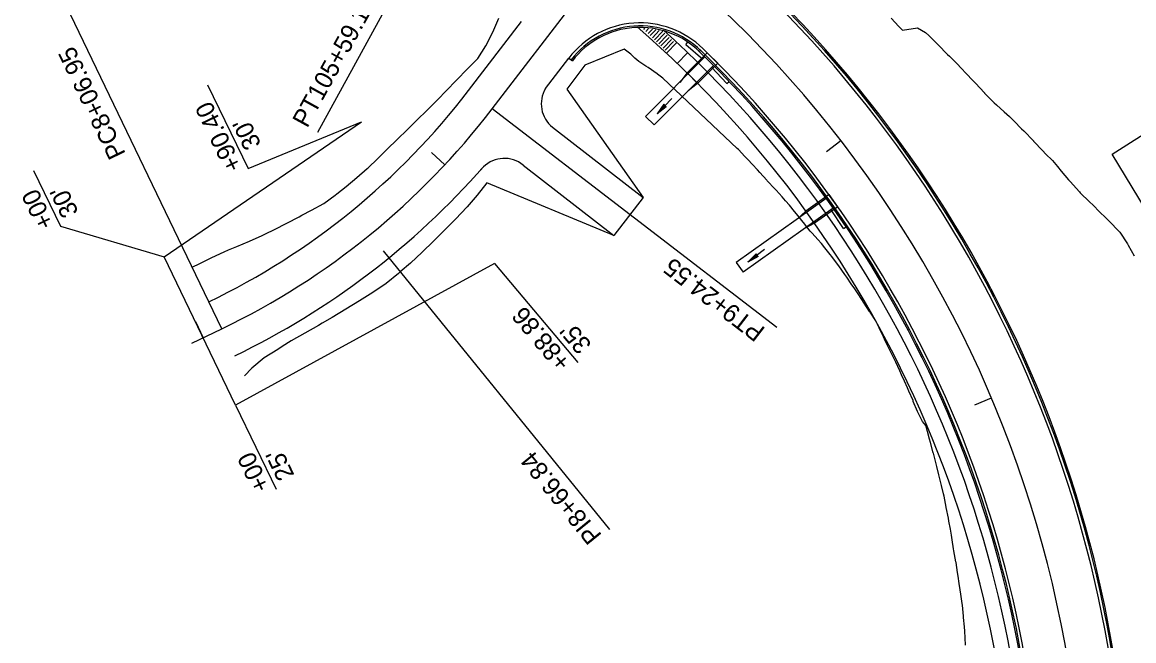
# Model space of a CAD drawing. Extents: x 1098669 to 1198896, y 698679 to 704410.
# Drawn here: x 1108421.2 to 1108793, y 699589.1 to 699795.9 of the extents above; entities that cross this region are included whole.
import ezdxf

# ---------------------------------------------------------------- set-up
doc = ezdxf.new("R2010")
doc.units = 0
for name, color, linetype in [('R_50 Horz Alg PC PI PT', 7, 'Continuous'), ('R_50 Horz Alg Ticks', 7, 'Continuous'), ('R_Horz Alg', 7, 'Continuous'), ('R_No Plot', 7, 'Continuous'), ('R_Proposed Const Limits', 7, 'Continuous'), ('R_Proposed Curb', 7, 'Continuous'), ('R_Proposed Road', 7, 'Continuous'), ('R_Proposed Sidewalk', 7, 'Continuous'), ('R_ROW', 7, 'Continuous'), ('R_ROW Annot', 7, 'Continuous'), ('R_Water', 7, 'Continuous')]:
    doc.layers.add(name, color=color, linetype=linetype)

msp = doc.modelspace()

# ---------------------------------------------------------------- linework, layer by layer
at = {"layer": 'R_50 Horz Alg PC PI PT'}
msp.add_line((1108574.89, 699859.09), (1108519.93, 699759.09), dxfattribs=at)
for points in [[(1108487.97, 699693.42), (1108435.87, 699801.52)], [(1108673.58, 699693.87), (1108578.4, 699766.94)], [(1108541.92, 699719.43), (1108617.62, 699626.32)], [(1108541.92, 699719.43), (1108617.62, 699626.32)]]:
    msp.add_lwpolyline(points, dxfattribs=at)
at = {"layer": 'R_50 Horz Alg Ticks'}
for points in [[(1108558.14, 699752.32), (1108562.52, 699748.22)], [(1108479.11, 699695.81), (1108481.71, 699690.41)]]:
    msp.add_lwpolyline(points, dxfattribs=at)
at = {"layer": 'R_Horz Alg'}
for p, q in [((1108578.4, 699766.94), (1108678.27, 699897.05)), ((1108690.25, 699752.74), (1108694.99, 699756.41)), ((1108477.94, 699688.59), (1108487.97, 699693.42)), ((1108739.88, 699668.02), (1108745.4, 699670.36))]:
    msp.add_line(p, q, dxfattribs=at)
for centre, radius, start, end in [((1108387.8, 699518.66), 388.45, 355.801, 61.2087), ((1108378.62, 699920.3), 251.85, 295.7332, 322.4881)]:
    msp.add_arc(centre, radius, start, end, dxfattribs=at)
at = {"layer": 'R_Proposed Const Limits'}
for points in [[(1108478.03, 699714.05), (1108480.54, 699715.23), (1108484.63, 699717.22), (1108488.74, 699719.19), (1108490.13, 699719.77), (1108492.98, 699720.95), (1108497.22, 699722.74), (1108501.43, 699724.64), (1108502.55, 699725.18), (1108505.59, 699726.66), (1108509.73, 699728.75), (1108513.86, 699730.89), (1108514.73, 699731.35), (1108517.98, 699733.09), (1108522.1, 699735.34), (1108525.85, 699738.1), (1108526.4, 699738.53), (1108529.49, 699741), (1108533.06, 699743.97), (1108536.62, 699746.98), (1108536.93, 699747.26), (1108539.99, 699750.19), (1108543.27, 699753.49), (1108546.65, 699756.7), (1108546.75, 699756.79), (1108550, 699759.94), (1108553.27, 699763.27), (1108556.52, 699766.44), (1108556.61, 699766.54), (1108559.94, 699769.85), (1108563.24, 699773.19), (1108566.23, 699776.28), (1108566.54, 699776.61), (1108570.04, 699780.22), (1108573.59, 699783.8), (1108576.29, 699788.03), (1108578.57, 699792.58), (1108580.65, 699797.29)], [(1108711.82, 699797.24), (1108714.39, 699794.49), (1108715.64, 699793.26), (1108720.62, 699793.99), (1108723.35, 699792.46), (1108724.43, 699791.42), (1108727.37, 699788.53), (1108727.6, 699788.3), (1108730.75, 699785.15), (1108731.35, 699784.55), (1108733.89, 699781.97), (1108735.3, 699780.52), (1108737.01, 699778.77), (1108739.22, 699776.45), (1108740.09, 699775.52), (1108743.05, 699772.3), (1108743.12, 699772.22), (1108746.27, 699769), (1108747.1, 699768.27), (1108749.69, 699765.94), (1108751.4, 699764.38), (1108753.04, 699762.8), (1108755.5, 699760.31), (1108756.25, 699759.55), (1108759.43, 699756.26), (1108759.52, 699756.16), (1108762.58, 699752.92), (1108763.49, 699751.94), (1108765.82, 699749.63), (1108767.47, 699747.7), (1108768.78, 699746.14), (1108771.17, 699743.25), (1108771.7, 699742.61), (1108774.85, 699739.18), (1108775.12, 699738.92), (1108778.23, 699735.87), (1108779.39, 699734.72), (1108781.61, 699732.52), (1108783.65, 699730.47), (1108784.98, 699729.14), (1108787.88, 699726.16), (1108788.32, 699725.71), (1108790.88, 699721.85), (1108791.18, 699721.32), (1108793.16, 699717.85)], [(1108622.58, 699786.85), (1108609.38, 699781.54), (1108606.34, 699777.57), (1108603.39, 699773.53), (1108628.92, 699737.28)], [(1108635.45, 699777.18), (1108633.67, 699778.55), (1108633.56, 699778.62), (1108630.53, 699780.72), (1108629.84, 699781.19), (1108627.47, 699782.76), (1108626.12, 699783.93), (1108624.77, 699785.2), (1108622.58, 699786.85)], [(1108736.78, 699587.68), (1108736.62, 699590.06), (1108736.46, 699592.3), (1108736.35, 699593.72), (1108736.11, 699596.92), (1108736.06, 699597.38), (1108735.7, 699601.03), (1108735.63, 699601.53), (1108735.19, 699604.66), (1108734.98, 699606.11), (1108734.66, 699608.29), (1108734.3, 699610.7), (1108734.11, 699611.93), (1108733.56, 699615.28), (1108733.51, 699615.55), (1108732.88, 699619.18), (1108732.77, 699619.87), (1108732.28, 699622.83), (1108732.01, 699624.47), (1108731.66, 699626.48), (1108731.21, 699629.09), (1108731.01, 699630.13), (1108730.32, 699633.68), (1108730.3, 699633.77), (1108729.58, 699637.42), (1108729.4, 699638.29), (1108728.74, 699641.03), (1108728.29, 699642.84), (1108727.84, 699644.64), (1108727.14, 699647.4), (1108726.92, 699648.24), (1108725.98, 699651.85), (1108725.95, 699651.95), (1108725.01, 699655.45), (1108724.73, 699656.5), (1108724.03, 699659.06), (1108723.48, 699661.07), (1108722.37, 699662.39), (1108720.98, 699665.09), (1108720.72, 699665.72), (1108719.28, 699669.14), (1108719.17, 699669.41), (1108717.82, 699672.55), (1108717.3, 699673.72), (1108716.3, 699675.94), (1108715.37, 699677.99), (1108714.75, 699679.32), (1108713.38, 699682.24), (1108713.17, 699682.68), (1108711.56, 699686.03), (1108711.34, 699686.46), (1108709.91, 699689.36), (1108709.29, 699690.69), (1108708.34, 699692.73), (1108707.29, 699694.94), (1108706.69, 699696.07), (1108704.81, 699698.93), (1108704.65, 699699.19), (1108702.62, 699702.31), (1108702.25, 699702.87), (1108700.58, 699705.42), (1108699.66, 699706.79), (1108698.51, 699708.5), (1108697.02, 699710.67), (1108696.4, 699711.56), (1108694.31, 699714.5), (1108694.25, 699714.59), (1108692, 699717.55), (1108691.47, 699718.23), (1108689.7, 699720.46), (1108688.54, 699721.9), (1108687.31, 699723.31), (1108685.42, 699725.42), (1108684.82, 699726.09), (1108682.52, 699728.98), (1108682.47, 699729.05), (1108680.22, 699731.87), (1108679.55, 699732.68), (1108677.86, 699734.71), (1108676.54, 699736.24), (1108675.43, 699737.49), (1108673.42, 699739.71), (1108672.94, 699740.23), (1108670.42, 699742.92), (1108670.24, 699743.12), (1108667.94, 699745.65), (1108667.1, 699746.56), (1108665.47, 699748.37), (1108663.97, 699749.98), (1108662.96, 699751.06), (1108660.75, 699753.34), (1108660.4, 699753.7), (1108635.45, 699777.18)], [(1108619.12, 699724.63), (1108576.63, 699742.26), (1108573.32, 699738.11), (1108570.01, 699734.18), (1108569.9, 699734.06), (1108566.23, 699730.23), (1108562.5, 699726.47), (1108559.06, 699723.07), (1108558.72, 699722.74), (1108554.95, 699718.98), (1108551.04, 699715.38), (1108547.63, 699712.41), (1108547.02, 699711.9), (1108542.9, 699708.53), (1108538.48, 699705.56), (1108534.92, 699703.31), (1108533.97, 699702.72), (1108529.42, 699699.98), (1108524.88, 699697.24), (1108521.55, 699695.27), (1108520.31, 699694.55), (1108515.72, 699691.93), (1108511.09, 699689.37), (1108508.11, 699687.44), (1108506.64, 699686.5), (1108502.1, 699683.75), (1108497.93, 699680.25), (1108495.58, 699677.64)]]:
    msp.add_lwpolyline(points, dxfattribs=at)
at = {"layer": 'R_Proposed Curb'}
msp.add_lwpolyline([(1108604.06, 699783.94), (1108605.25, 699783.03)], dxfattribs=at)
for centre, radius, start, end in [((1108387.8, 699518.66), 403.45, 356.4859, 47.1913), ((1108387.8, 699518.66), 403.95, 356.5551, 47.1913), ((1108627.85, 699765.67), 29, 45.5223, 142.4881), ((1108627.85, 699765.67), 28.5, 45.5223, 142.4881), ((1108387.8, 699518.66), 372.95, 355.801, 45.8755), ((1108387.8, 699518.66), 373.45, 355.801, 45.8755)]:
    msp.add_arc(centre, radius, start, end, dxfattribs=at)
at = {"layer": 'R_Proposed Road'}
for p, q in [((1108570.46, 699773.03), (1108588.19, 699796.12)), ((1108596.23, 699773.75), (1108604.06, 699783.94))]:
    msp.add_line(p, q, dxfattribs=at)
for points in [[(1108598.54, 699760.81), (1108628.92, 699737.28)], [(1108588.74, 699748.16), (1108619.12, 699724.63)], [(1108628.92, 699737.28), (1108619.12, 699724.63)]]:
    msp.add_lwpolyline(points, dxfattribs=at)
for centre, radius, start, end in [((1108387.8, 699518.66), 402.45, 356.147, 47.1809), ((1108627.85, 699765.67), 30, 45.5223, 142.4881), ((1108387.8, 699518.66), 374.45, 355.801, 45.8755), ((1108378.62, 699920.3), 241.85, 295.7332, 322.4881), ((1108604.81, 699768.6), 10, 149.0142, 231.1783), ((1108582.46, 699740.38), 10, 51.0896, 134.2395), ((1108378.62, 699920.3), 261.85, 295.7332, 318.7319), ((1108484.79, 699840.68), 130, 313.5954, 314.2395)]:
    msp.add_arc(centre, radius, start, end, dxfattribs=at)
at = {"layer": 'R_Proposed Sidewalk'}
for p, q in [((1108629.08, 699793.5), (1108629.44, 699793.88)), ((1108629.8, 699792.81), (1108630.73, 699793.77)), ((1108630.52, 699792.12), (1108631.99, 699793.64)), ((1108631.25, 699791.42), (1108633.09, 699793.34)), ((1108631.97, 699790.73), (1108634.29, 699793.14)), ((1108632.69, 699790.04), (1108635.46, 699792.92)), ((1108633.41, 699789.34), (1108636.18, 699792.23)), ((1108634.13, 699788.65), (1108636.9, 699791.53)), ((1108634.85, 699787.96), (1108637.62, 699790.84)), ((1108635.57, 699787.26), (1108638.34, 699790.15)), ((1108636.29, 699786.57), (1108639.06, 699789.45)), ((1108636.67, 699785.52), (1108640.12, 699789.14)), ((1108640.29, 699782.07), (1108643.74, 699785.68))]:
    msp.add_line(p, q, dxfattribs=at)
for radius, start, end in [(364.95, 357.0396, 49.0755), (369.95, 357.5039, 47.9185)]:
    msp.add_arc((1108387.8, 699518.66), radius, start, end, dxfattribs=at)
at = {"layer": 'R_ROW'}
msp.add_line((1108866.06, 699619), (1108785.8, 699751.82), dxfattribs=at)
for points in [[(1108468.69, 699717.43), (1108534.72, 699762.65)], [(1108492.57, 699667.89), (1108468.69, 699717.43)], [(1108579.21, 699715.24), (1108492.57, 699667.89)]]:
    msp.add_lwpolyline(points, dxfattribs=at)
at = {"layer": 'R_ROW Annot'}
for p, q in [((1108785.8, 699751.82), (1108834.27, 699782.56)), ((1108483.14, 699775), (1108496.7, 699746.96)), ((1108424.96, 699746.28), (1108433.94, 699727.71)), ((1108579.21, 699715.24), (1108607.09, 699682.16)), ((1108492.57, 699667.89), (1108506.14, 699639.82))]:
    msp.add_line(p, q, dxfattribs=at)
for points in [[(1108496.7, 699746.96), (1108534.72, 699762.65)], [(1108433.94, 699727.71), (1108468.69, 699717.43)]]:
    msp.add_lwpolyline(points, dxfattribs=at)
at = {"layer": 'R_Water'}
for p, q in [((1108643.21, 699788.51), (1108643.87, 699789.27)), ((1108643.21, 699788.51), (1108648.84, 699783.57)), ((1108649.58, 699784.3), (1108629.73, 699764.38)), ((1108650.28, 699785.72), (1108643.58, 699778.99)), ((1108652.77, 699781.13), (1108649.22, 699784.66)), ((1108653.83, 699782.19), (1108650.66, 699785.34)), ((1108652.41, 699781.48), (1108632.57, 699761.56)), ((1108653.83, 699782.19), (1108647.12, 699775.46)), ((1108656.94, 699775.41), (1108651.78, 699780.84)), ((1108643.58, 699778.99), (1108641.11, 699775.8)), ((1108647.12, 699775.46), (1108643.58, 699778.99)), ((1108647.12, 699775.46), (1108643.58, 699778.99)), ((1108656.94, 699775.41), (1108657.67, 699776.09)), ((1108647.12, 699775.46), (1108643.94, 699772.98)), ((1108638.51, 699770.43), (1108633.57, 699765.31)), ((1108635.82, 699768.46), (1108633.57, 699765.31)), ((1108635.82, 699768.46), (1108633.57, 699765.31)), ((1108635.89, 699768.4), (1108634.02, 699765.77)), ((1108635.89, 699768.4), (1108634.02, 699765.77)), ((1108635.96, 699768.33), (1108634.47, 699766.25)), ((1108635.96, 699768.33), (1108634.47, 699766.25)), ((1108636.64, 699767.67), (1108635.82, 699768.46)), ((1108636.64, 699767.67), (1108635.82, 699768.46)), ((1108636.64, 699767.67), (1108633.57, 699765.31)), ((1108636.64, 699767.67), (1108633.57, 699765.31)), ((1108636.57, 699767.73), (1108634.02, 699765.77)), ((1108636.57, 699767.73), (1108634.02, 699765.77)), ((1108636.5, 699767.8), (1108634.47, 699766.25)), ((1108636.5, 699767.8), (1108634.47, 699766.25)), ((1108636.03, 699768.26), (1108634.92, 699766.7)), ((1108636.03, 699768.26), (1108634.92, 699766.7)), ((1108636.44, 699767.87), (1108634.92, 699766.7)), ((1108636.44, 699767.87), (1108634.92, 699766.7)), ((1108636.1, 699768.19), (1108635.37, 699767.17)), ((1108636.1, 699768.19), (1108635.37, 699767.17)), ((1108636.36, 699767.94), (1108635.37, 699767.17)), ((1108636.36, 699767.94), (1108635.37, 699767.17)), ((1108636.17, 699768.13), (1108635.81, 699767.63)), ((1108636.17, 699768.13), (1108635.81, 699767.63)), ((1108636.3, 699768), (1108635.81, 699767.63)), ((1108636.3, 699768), (1108635.81, 699767.63)), ((1108632.57, 699761.56), (1108629.73, 699764.38)), ((1108690.17, 699737), (1108659.98, 699715.57)), ((1108691.1, 699738.27), (1108683.36, 699732.77)), ((1108692.77, 699733.33), (1108689.88, 699737.4)), ((1108694, 699734.2), (1108691.1, 699738.27)), ((1108692.48, 699733.74), (1108662.3, 699712.31)), ((1108683.36, 699732.77), (1108680.38, 699730.05)), ((1108686.25, 699728.7), (1108683.36, 699732.77)), ((1108686.25, 699728.7), (1108683.36, 699732.77)), ((1108694, 699734.2), (1108686.25, 699728.7)), ((1108695.94, 699727), (1108691.75, 699733.21)), ((1108696.77, 699727.55), (1108692.77, 699733.33)), ((1108686.25, 699728.7), (1108682.7, 699726.79)), ((1108695.94, 699727), (1108696.77, 699727.55)), ((1108669.51, 699719.91), (1108663.95, 699715.73)), ((1108666.66, 699718.49), (1108663.95, 699715.73)), ((1108666.66, 699718.49), (1108663.95, 699715.73)), ((1108667.35, 699717.57), (1108663.95, 699715.73)), ((1108667.35, 699717.57), (1108663.95, 699715.73)), ((1108666.72, 699718.41), (1108664.46, 699716.11)), ((1108666.72, 699718.41), (1108664.46, 699716.11)), ((1108667.29, 699717.64), (1108664.46, 699716.11)), ((1108667.29, 699717.64), (1108664.46, 699716.11)), ((1108666.77, 699718.33), (1108664.98, 699716.51)), ((1108666.77, 699718.33), (1108664.98, 699716.51)), ((1108667.23, 699717.72), (1108664.98, 699716.51)), ((1108667.23, 699717.72), (1108664.98, 699716.51)), ((1108666.83, 699718.25), (1108665.49, 699716.89)), ((1108666.83, 699718.25), (1108665.49, 699716.89)), ((1108667.17, 699717.8), (1108665.49, 699716.89)), ((1108667.17, 699717.8), (1108665.49, 699716.89)), ((1108666.89, 699718.18), (1108666.01, 699717.28)), ((1108666.89, 699718.18), (1108666.01, 699717.28)), ((1108667.11, 699717.88), (1108666.01, 699717.28)), ((1108667.11, 699717.88), (1108666.01, 699717.28)), ((1108666.95, 699718.1), (1108666.52, 699717.66)), ((1108666.95, 699718.1), (1108666.52, 699717.66)), ((1108667.06, 699717.95), (1108666.52, 699717.66)), ((1108667.06, 699717.95), (1108666.52, 699717.66)), ((1108667.35, 699717.57), (1108666.66, 699718.49)), ((1108667.35, 699717.57), (1108666.66, 699718.49))]:
    msp.add_line(p, q, dxfattribs=at)
msp.add_lwpolyline([(1108659.98, 699715.57), (1108662.3, 699712.31)], dxfattribs=at)

# ---------------------------------------------------------------- texts
at = {"layer": 'R_50 Horz Alg PC PI PT'}
for s, rotation, p in [('PT105+59.12', 61.2087, (1108516.51, 699760.29)), ('PC8+06.95', 115.7332, (1108455.89, 699751.93)), ('PT9+24.55', 142.4881, (1108670.09, 699693.45)), ('PI8+66.84', 129.1107, (1108615.3, 699624.42)), ('PI8+66.84', 129.1107, (1108615.3, 699624.42))]:
    msp.add_text(s, height=6, rotation=rotation, dxfattribs=at).set_placement(p)
at = {"layer": 'R_No Plot'}
msp.add_text('+', height=0.1, rotation=135.1131, dxfattribs=at).set_placement((1108662, 699793.88))
at = {"layer": 'R_ROW Annot'}
for s, rotation, p in [('+90.40', 115.8049, (1108494.96, 699747.65)), ("30'", 115.8049, (1108501.23, 699755.07)), ('+00', 115.8049, (1108432.04, 699728.45)), ("30'", 115.8049, (1108440.14, 699732.37)), ('+88.86', 130.1201, (1108605.05, 699682.41)), ("35'", 130.1201, (1108611.94, 699688.21)), ('+00', 115.8049, (1108504.23, 699640.57)), ("25'", 115.8049, (1108512.33, 699644.48))]:
    msp.add_text(s, height=6, rotation=rotation, dxfattribs=at).set_placement(p)

doc.saveas('drawing.dxf')
